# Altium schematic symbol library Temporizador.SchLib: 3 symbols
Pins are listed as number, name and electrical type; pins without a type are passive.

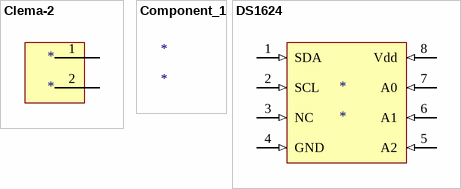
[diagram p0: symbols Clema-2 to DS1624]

## Clema-2
designator *
footprint Clema-2
pins: 1 0 (power) "+", 2 1 (power) "+"

## Component_1
designator *

## DS1624
designator *
footprint DIP-8
pins: 1 SDA (in), 2 SCL (in), 3 NC (in), 4 GND (in), 5 A2 (in), 6 A1 (in), 7 A0 (in), 8 Vdd (in)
